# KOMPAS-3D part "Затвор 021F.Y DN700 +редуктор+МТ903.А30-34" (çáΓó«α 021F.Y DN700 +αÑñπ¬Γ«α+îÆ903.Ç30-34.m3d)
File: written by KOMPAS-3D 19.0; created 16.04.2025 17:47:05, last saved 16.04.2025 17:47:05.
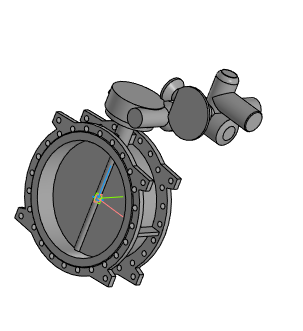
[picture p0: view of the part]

Document properties: Полное имя файла: Затвор 021F.Y DN700 +редуктор+МТ903.А30-34.a3d

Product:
- Part/product: Затвор 021F.Y DN700 +редуктор+МТ903.А30-34
    Масса: 639.932

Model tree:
1. Операция без истории:1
